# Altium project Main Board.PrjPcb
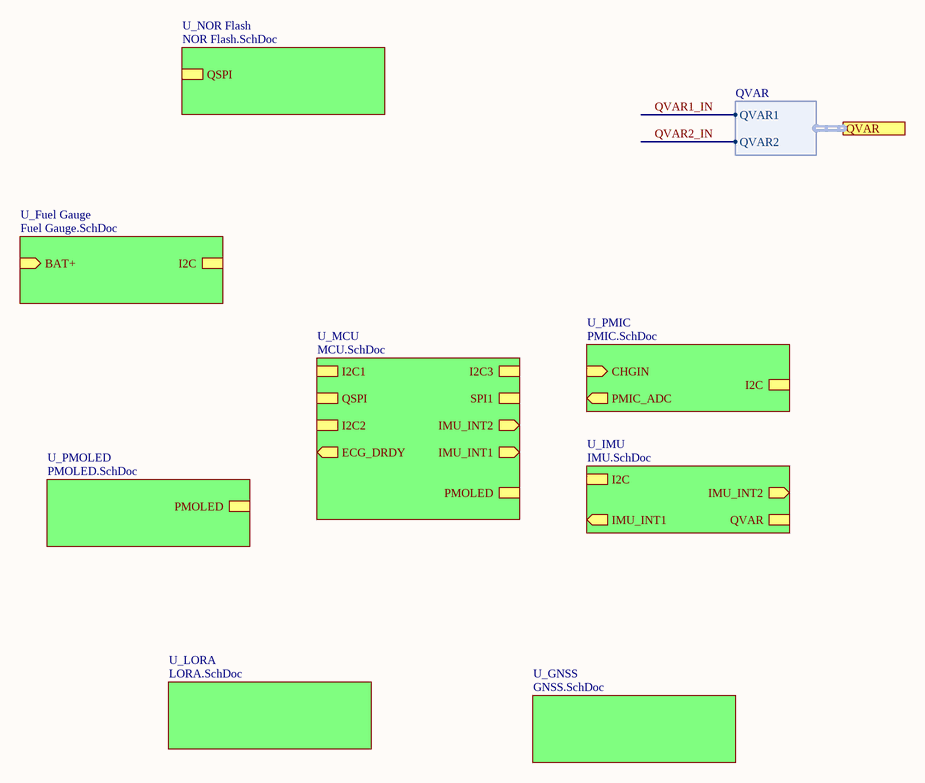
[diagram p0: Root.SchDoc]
9 sheets, 84 parts. Net scope: hierarchical (ports join the sheet entries above them; power ports are global).
Board file: Main Board.PcbDoc
Sheets:
  Root.SchDoc
    U_PMIC = PMIC.SchDoc
    U_MCU = MCU.SchDoc
    U_IMU = IMU.SchDoc
    U_Fuel Gauge = Fuel Gauge.SchDoc
    U_NOR Flash = NOR Flash.SchDoc
    U_PMOLED = PMOLED.SchDoc
    U_GNSS = GNSS.SchDoc
    U_LORA = LORA.SchDoc

## Sheet Root.SchDoc
size A4; SheetNumber: 1; SheetTotal: 9

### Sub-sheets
U_Fuel Gauge = Fuel Gauge.SchDoc: BAT+ (in), I2C (harness I2C)
U_GNSS = GNSS.SchDoc: no entries
U_IMU = IMU.SchDoc: I2C (harness I2C), IMU_INT1 (out), IMU_INT2 (out), QVAR (harness QVAR)
U_LORA = LORA.SchDoc: no entries
U_MCU = MCU.SchDoc: I2C3 (harness I2C), I2C1 (harness I2C), QSPI (harness QSPI), I2C2 (harness I2C), ECG_DRDY (out), IMU_INT1 (out), IMU_INT2 (out), SPI1 (harness SPI), PMOLED (harness PMOLED)
U_NOR Flash = NOR Flash.SchDoc: QSPI (harness QSPI)
U_PMIC = PMIC.SchDoc: CHGIN (in), I2C (harness I2C), PMIC_ADC (out)
U_PMOLED = PMOLED.SchDoc: PMOLED (harness PMOLED)

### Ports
QVAR (harness QVAR)

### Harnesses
QVAR: QVAR2, QVAR1

## Sheet PMIC.SchDoc
size A4; SheetNumber: 3; SheetTotal: 9
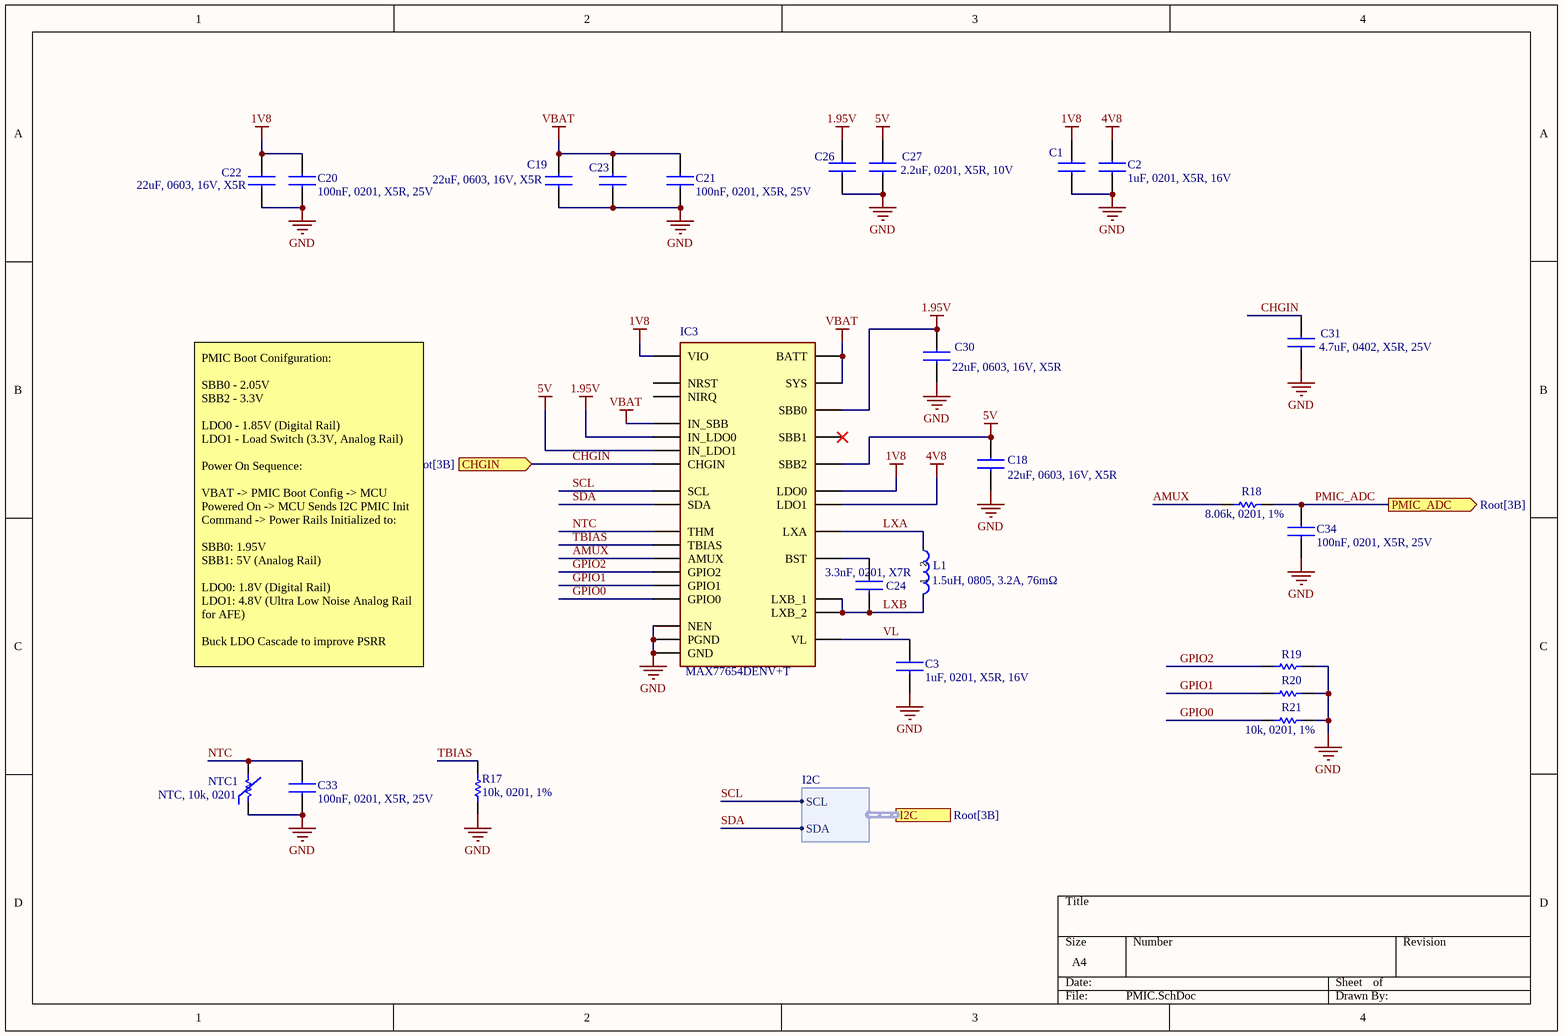
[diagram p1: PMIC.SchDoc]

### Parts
C1  1uF, 0201, X5R, 16V  [CL03A105MQ3CSNH]  (value not drawn)
C2  1uF, 0201, X5R, 16V  [CL03A105MQ3CSNH]
C3  1uF, 0201, X5R, 16V  [CL03A105MQ3CSNH]
C18  22uF, 0603, 16V, X5R  [CAPC1608X80N]
C19  22uF, 0603, 16V, X5R  [CAPC1608X80N]
C20  100nF, 0201, X5R, 25V  [CL03A104KO3NNNC]
C21  100nF, 0201, X5R, 25V  [CL03A104KO3NNNC]
C22  22uF, 0603, 16V, X5R  [CAPC1608X80N]
C23  22uF, 0603, 16V, X5R  [CAPC1608X80N]  (value not drawn)
C24  3.3nF, 0201, X7R  [GCM033R71E332KE02D]
C26  2.2uF, 0201, X5R, 10V  [GRM033R61A225ME47D]  (value not drawn)
C27  2.2uF, 0201, X5R, 10V  [GRM033R61A225ME47D]
C30  22uF, 0603, 16V, X5R  [CAPC1608X80N]
C31  4.7uF, 0402, X5R, 25V  [CL05A106MP5NUNC]
C33  100nF, 0201, X5R, 25V  [CL03A104KO3NNNC]
C34  100nF, 0201, X5R, 25V  [CL03A104KO3NNNC]
IC3  MAX77654DENV+T  [BGA30C40P6X5_279X234X50]
L1  1.5uH, 0805, 3.2A, 76mΩ  [MTQH201210S1R5MBT]
NTC1  NTC, 10k, 0201  [NCP03XH103F05RL]
R17  10k, 0201, 1%  [RC0201FR-0710KL]
R18  8.06k, 0201, 1%  [RC0201FR-078K06L]
R19  10k, 0201, 1%  [RC0201FR-0710KL]  (value not drawn)
R20  10k, 0201, 1%  [RC0201FR-0710KL]  (value not drawn)
R21  10k, 0201, 1%  [RC0201FR-0710KL]

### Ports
CHGIN (in, see Root[3B]), I2C (harness I2C, see Root[3B]), PMIC_ADC (out, see Root[3B])

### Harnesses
I2C: SDA, SCL

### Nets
1.95V: C26.2 C30.2 IC3.B6(IN_LDO0) IC3.C6(SBB0)
1V8: C1.2 C20.2 C22.2 IC3.A4(VIO) IC3.B5(LDO0)
4V8: C2.2 IC3.A5(LDO1)
5V: C18.2 C27.2 IC3.A6(IN_LDO1) IC3.D4(SBB2)
GND: C1.1 C2.1 C3.1 C18.1 C19.1 C20.1 C21.1 C22.1 C23.1 C26.1 C27.1 C30.1 C31.1 C33.1 C34.1 IC3.B3(NEN) IC3.C3(GND) IC3.E6(PGND) NTC1.1 R17.1 R19.1 R20.1 R21.1  [project net SDO]
VBAT: C19.2 C21.2 C23.2 IC3.E2(SYS) IC3.E3(BATT) IC3.E4(IN_SBB)  [project net I_SENSE_N]
AMUX: IC3.C1(AMUX) R18.1
CHGIN: C31.2 IC3.E1(CHGIN) ; port CHGIN
GPIO0: IC3.B1(GPIO0) R21.2
GPIO1: IC3.A1(GPIO1) R20.2
GPIO2: IC3.C2(GPIO2) R19.2
LXA: IC3.E5(LXA) L1.2
LXB: C24.1 IC3.C5(LXB_1) IC3.D5(LXB_2) L1.1
NTC: C33.2 IC3.D2(THM) NTC1.2
PMIC_ADC: C34.2 R18.2 ; port PMIC_ADC
SCL: IC3.B4(SCL) ; port I2C.SCL
SDA: IC3.A3(SDA) ; port I2C.SDA
TBIAS: IC3.D3(TBIAS) R17.2
VL: C3.2 IC3.D1(VL)
NetC24_2: C24.2 IC3.D6(BST)

Not connected (* = marked no-connect by the designer): IC3 A2(NRST) B2(NIRQ) C4(SBB1)*

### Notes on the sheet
- PMIC Boot Conifguration:
  SBB0 - 2.05V
  SBB2 - 3.3V
  LDO0 - 1.85V (Digital Rail)
  LDO1 - Load Switch (3.3V, Analog Rail)
  Power On Sequence:
  VBAT -> PMIC Boot Config -> MCU Powered On -> MCU Sends I2C PMIC Init Command -> Power Rails Initialized to:
  SBB0: 1.95V
  SBB1: 5V (Analog Rail)
  LDO0: 1.8V (Digital Rail)
  LDO1: 4.8V (Ultra Low Noise Analog Rail                                                              for AFE)
  Buck LDO Cascade to improve PSRR

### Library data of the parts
C1-C3 = GRM033R61C105ME15D: Manufacturer_Name: muRata
C18 C19 C22 C23 C30 = CL10A226MO7JZNC: Multilayer Ceramic Capacitors MLCC - SMD/SMT 22uF+/-20% 16V X5R 1608; Manufacturer_Name: SAMSUNG
C20 C21 C33 C34 = CL03A104KO3NNNC: CAP CER 100nF 25V X5R 0201; Manufacturer_Name: SAMSUNG; Manu Part #: CL03A104KA3NNNC
C24 = GCM033R71E332KE02D: Manufacturer_Name: Murata Electronics
C26 C27 = GRM033R61A225ME47D: Manufacturer_Name: Murata Electronics
C31 = GRM155R61E475ME15D: 4.7uF ±20% 25V Ceramic Capacitor X5R 0402
IC3 = MAX77654DENV+T: Power Management Specialised - PMIC Ultra Low Power PMIC w/ 3-Output SIMO + Linear Charger; Manufacturer_Name: Analog Devices
L1 = MTQH201210S1R5MBT: 1.5uH 2.6A 3.2A 76mΩ Molded Inductor ±20% 0805 Power Inductors ROHS; Manufacturer: MetalLions; ki_keywords: C17701177 L0805 MTQH201210S1R5MBT MetalLions
NTC1 = NCP03XH103F05RL: THERMISTOR NTC 10kΩ 3380K 0201; Manufacturer_Name: Murata Electronics
R17 R19-R21 = RC0201FR-0710KL
R18 = RC0201FR-078K06L: Manufacturer_Name: Yageo Group

## Sheet MCU.SchDoc
size C; SheetNumber: 2; SheetTotal: 8
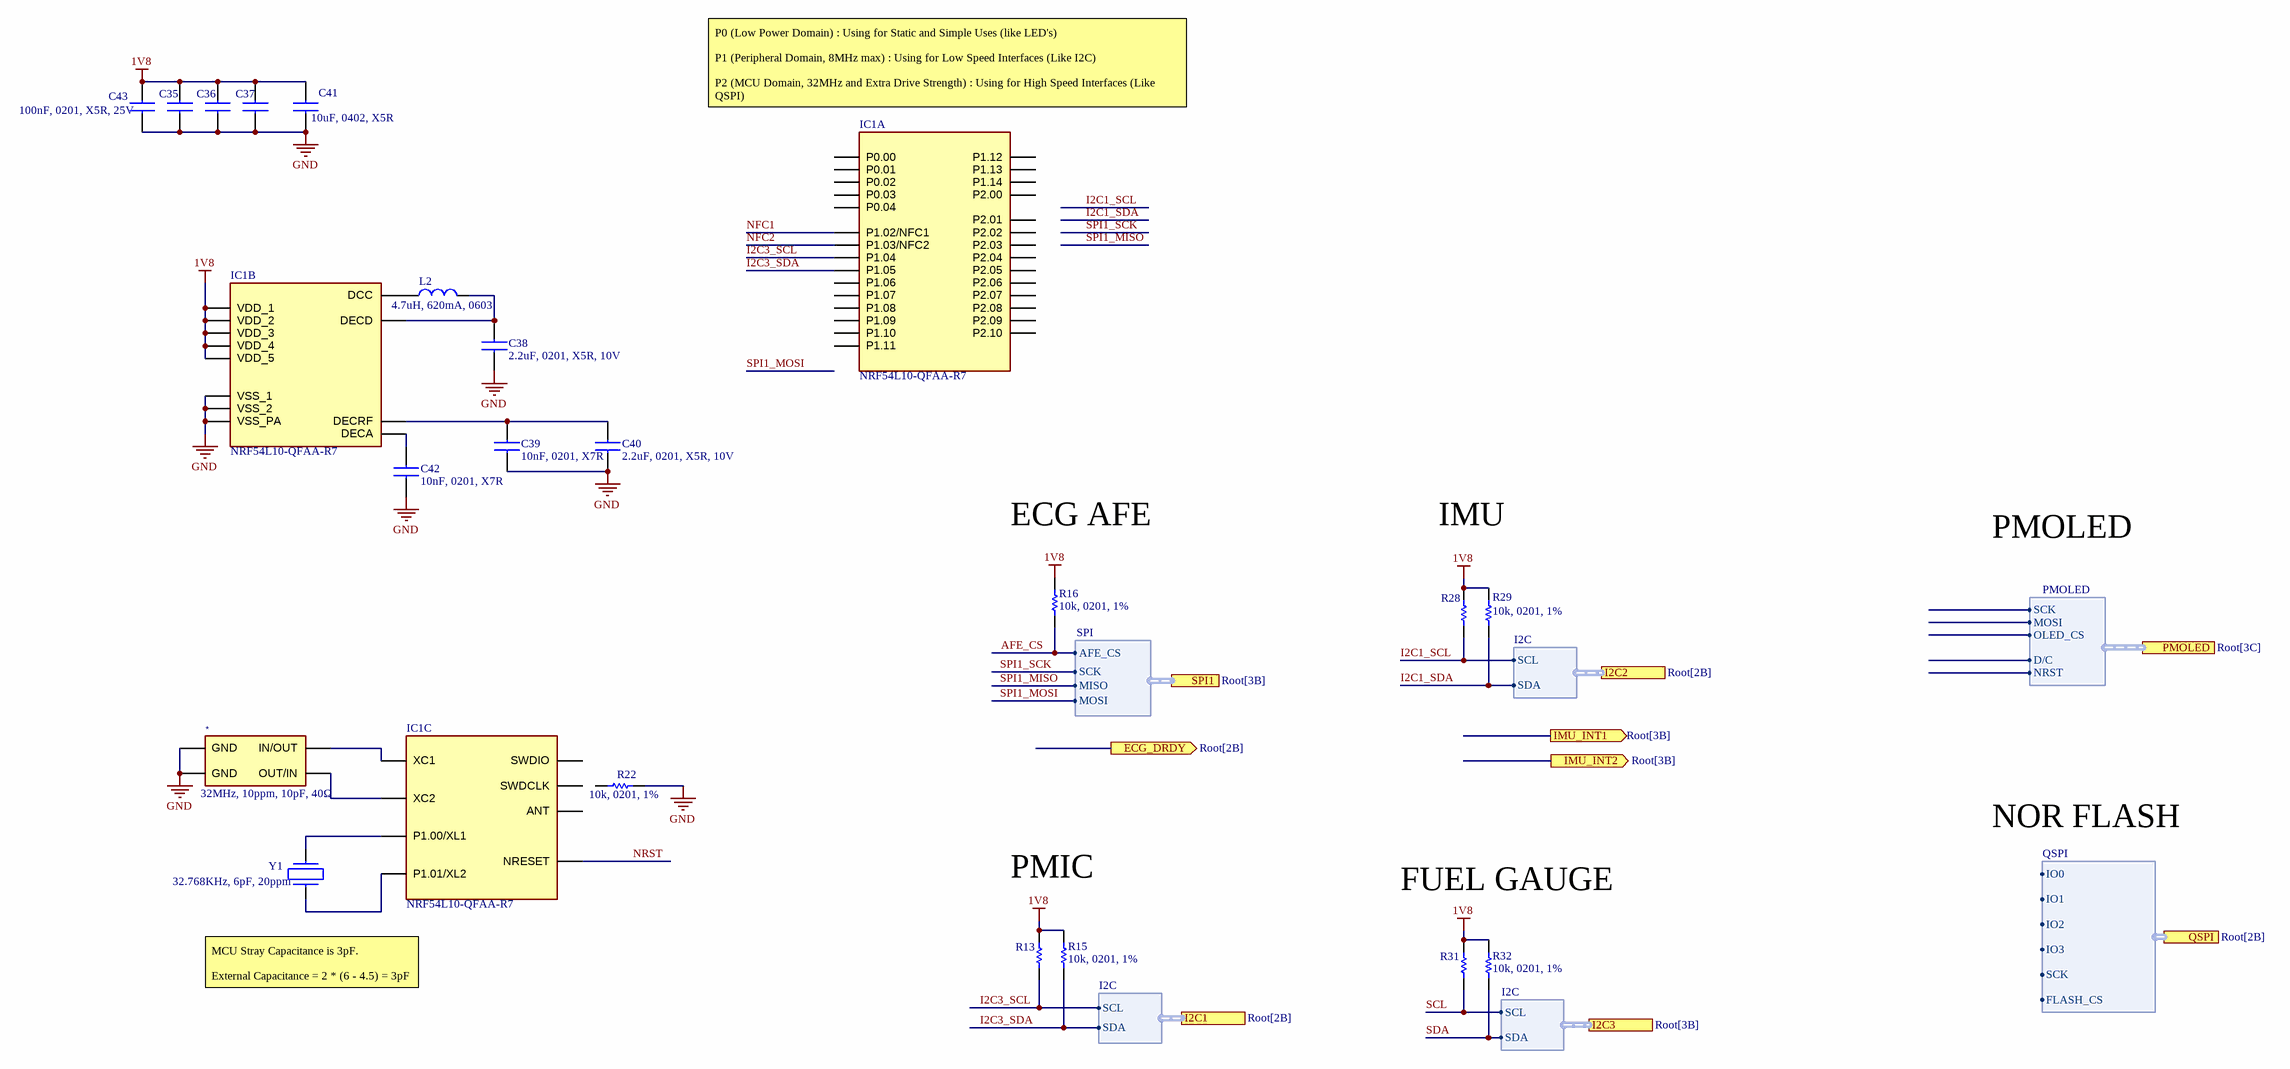
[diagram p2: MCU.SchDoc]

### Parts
(Parts that share a designator on the sheet are numbered #1, #2 ... from top to bottom, then left to right.)
*#1  32MHz, 10ppm, 10pF, 40Ω  [Q24FA20H0021700]
C35  100nF, 0201, X5R, 25V  [CL03A104KO3NNNC]  (value not drawn)
C36  100nF, 0201, X5R, 25V  [CL03A104KO3NNNC]  (value not drawn)
C37  100nF, 0201, X5R, 25V  [CL03A104KO3NNNC]  (value not drawn)
C38  2.2uF, 0201, X5R, 10V  [GRM033R61A225ME47D]
C39  10nF, 0201, X7R  [CL03A105MQ3CSNH]
C40  2.2uF, 0201, X5R, 10V  [GRM033R61A225ME47D]
C41  10uF, 0402, X5R  [CL05A106MP5NUNC]
C42  10nF, 0201, X7R  [CL03A105MQ3CSNH]
C43  100nF, 0201, X5R, 25V  [CL03A104KO3NNNC]
IC1  NRF54L10-QFAA-R7  [NRF54L10-QFAA-R7]  (parts A,B,C of 3)
L2  4.7uH, 620mA, 0603  [LQM18PH1R0MFRB]
R13  10k, 0201, 1%  [RC0201FR-0710KL]  (value not drawn)
R15  10k, 0201, 1%  [RC0201FR-0710KL]
R16  10k, 0201, 1%  [RC0201FR-0710KL]
R22  10k, 0201, 1%  [RC0201FR-0710KL]
R28  10k, 0201, 1%  [RC0201FR-0710KL]  (value not drawn)
R29  10k, 0201, 1%  [RC0201FR-0710KL]
R31  10k, 0201, 1%  [RC0201FR-0710KL]  (value not drawn)
R32  10k, 0201, 1%  [RC0201FR-0710KL]
Y1  32.768KHz, 6pF, 20ppm  [Q13FC1350004900]

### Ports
ECG_DRDY (out, see Root[2B]), I2C1 (harness I2C, see Root[2B]), I2C2 (harness I2C, see Root[2B]), I2C3 (harness I2C, see Root[3B]), IMU_INT1 (out, see Root[3B]), IMU_INT2 (out, see Root[3B]), PMOLED (harness PMOLED, see Root[3C]), QSPI (harness QSPI, see Root[2B]), SPI1 (harness SPI, see Root[3B])

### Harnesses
I2C: SCL, SDA
SPI: MOSI, MISO, SCK, AFE_CS
I2C: SDA, SCL
QSPI: FLASH_CS, SCK, IO3, IO2, IO1, IO0
PMOLED: SCK, MOSI, OLED_CS, NRST, D/C

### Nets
1V8: C35.2 C36.2 C37.2 C41.1 C43.2 IC1.10(VDD_1) IC1.22(VDD_2) IC1.36(VDD_3) IC1.47(VDD_4) IC1.48(VDD_5) R13.2 R15.2 R16.2 R28.2 R29.2 R31.2 R32.2
GND: *#1.2(GND) *#1.4(GND) C35.1 C36.1 C37.1 C38.1 C39.1 C40.1 C41.2 C42.1 C43.1 IC1.32(VSS_PA) IC1.44(VSS_1) IC1.49(VSS_2) R22.2  [project net SDO]
AFE_CS: R16.1 ; port SPI1.AFE_CS
I2C1_SCL: R28.1 ; port I2C2.SCL
I2C1_SDA: R29.1 ; port I2C2.SDA
I2C3_SCL: IC1.5(P1.04) R13.1 ; port I2C1.SCL
I2C3_SDA: IC1.6(P1.05) R15.1 ; port I2C1.SDA
NFC1: IC1.3(P1.02/NFC1)
NFC2: IC1.4(P1.03/NFC2)
NRST: IC1.30(NRESET)
SCL: R31.1 ; port I2C3.SCL
SDA: R32.1 ; port I2C3.SDA
Net*#1_1: *#1.1(IN/OUT) IC1.34(XC1)
Net*#1_3: *#1.3(OUT/IN) IC1.35(XC2)
NetC38_2: C38.2 IC1.45(DECD) L2.2
NetC39_2: C39.2 C40.2 IC1.33(DECRF)
NetC42_2: C42.2 IC1.43(DECA)
NetIC1_1: IC1.1(P1.00/XL1) Y1.2
NetIC1_2: IC1.2(P1.01/XL2) Y1.1
NetIC1_46: IC1.46(DCC) L2.1

Not connected (* = marked no-connect by the designer): IC1 7(P1.06) 8(P1.07) 9(P1.08) 11(P2.00) 12(P2.01) 13(P2.02) 14(P2.03) 15(P2.04) 16(P2.05) 17(P2.06) 18(P2.07) 19(P2.08) 20(P2.09) 21(P2.10) 23(P0.00) 24(P0.01) 25(SWDIO) 26(SWDCLK) 27(P0.02) 28(P0.03) 29(P0.04) 31(ANT) 37(P1.09) 38(P1.10) 39(P1.11) 40(P1.12) 41(P1.13) 42(P1.14); R22 1

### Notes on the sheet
- P0 (Low Power Domain) : Using for Static and Simple Uses (like LED's)
  P1 (Peripheral Domain, 8MHz max) : Using for Low Speed Interfaces (Like I2C)
  P2 (MCU Domain, 32MHz and Extra Drive Strength) : Using for High Speed Interfaces (Like QSPI)
- ECG AFE
- IMU
- PMOLED
- PMIC
- NOR FLASH
- FUEL GAUGE
- MCU Stray Capacitance is 3pF.
  External Capacitance = 2 * (6 - 4.5) = 3pF

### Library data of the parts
*#1 = Q24FA20H0021700: -40℃~+85℃ 10pF 32MHz 40Ω Crystal Oscillator ±10ppm ±20ppm SMD2520-4P Crystals ROHS; Manufacturer: Seiko Epson
C35-C37 C43 = CL03A104KO3NNNC: as C20 on sheet PMIC
C38 C40 = GRM033R61A225ME47D: Manufacturer_Name: Murata Electronics
C39 C42 = CC0201KRX7R8BB103: Manufacturer_Name: YAGEO
C41 = CL05A106MP5NUNC: Manufacturer_Name: SAMSUNG
IC1 = NRF54L10-QFAA-R7: IC RF TxRx + MCU 802.15.4, Bluetooth Bluetooth v6.0, Matter, Thread 48-VFQFN Exposed Pad; Manufacturer_Name: Nordic Semiconductor
L2 = LQM18PN4R7MFRL: FIXED IND 4.7uH 620mA 440mΩ 0603; Manufacturer_Name: Murata Electronics
R13 R15 R16 R22 R28 R29 R31 R32 = RC0201FR-0710KL
Y1 = Q13FC1350004900: -40℃~+85℃ 32.768kHz 6pF 70kΩ Crystal Oscillator ±20ppm SMD3215-2P Crystals ROHS; Manufacturer: Seiko Epson

## Sheet IMU.SchDoc
size A; SheetNumber: 5; SheetTotal: 8
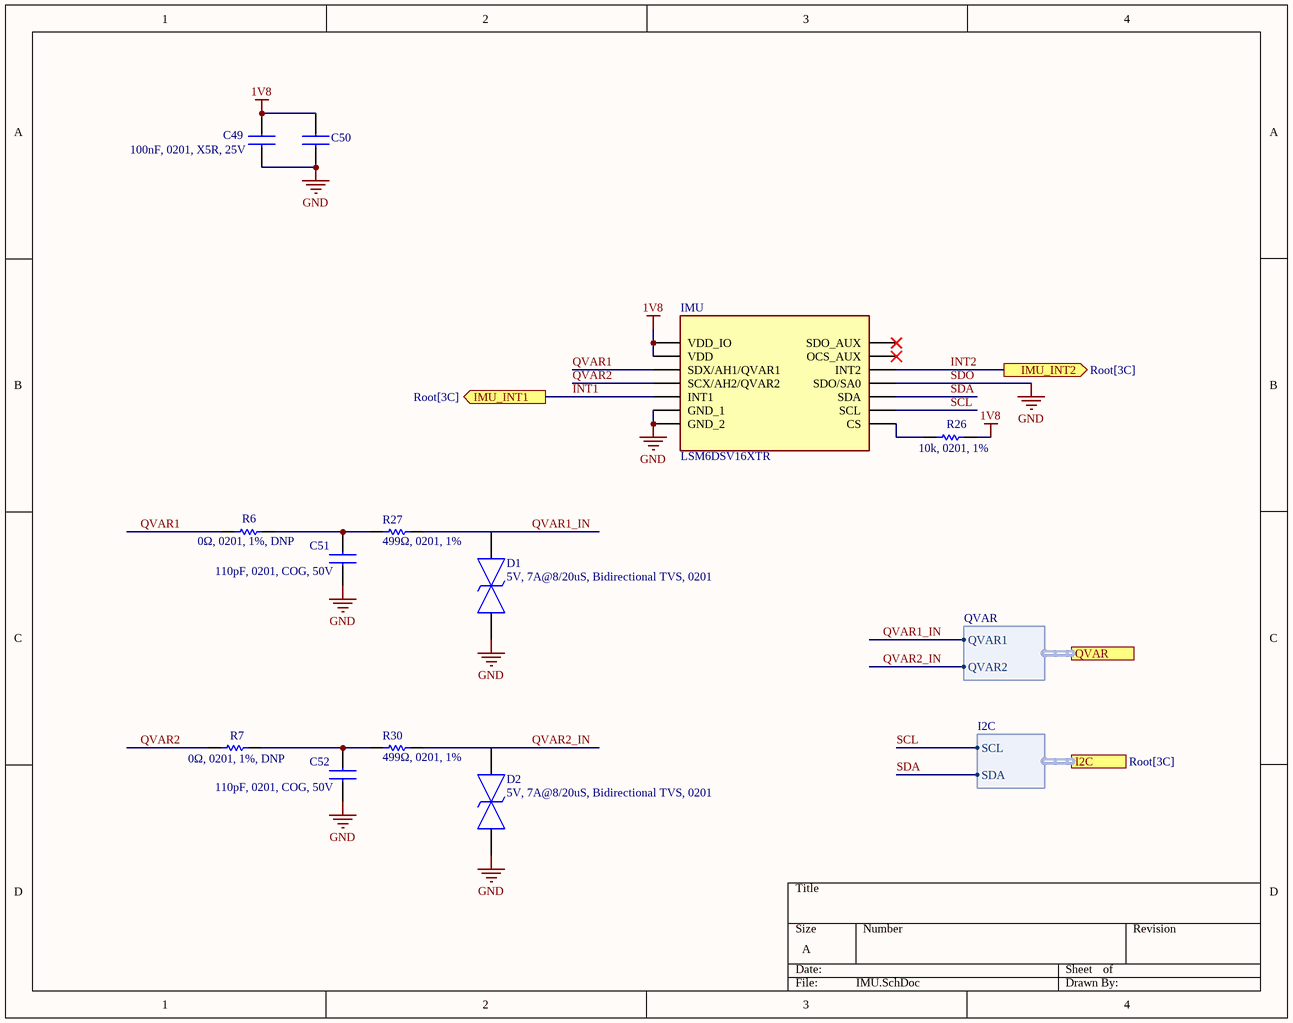
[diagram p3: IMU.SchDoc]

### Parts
C49  100nF, 0201, X5R, 25V  [CL03A104KO3NNNC]
C50  CL03A104KO3NNNC  [CL03A104KO3NNNC]  (value not drawn)
C51  110pF, 0201, COG, 50V  [GRM0335C1H111GA01D]
C52  110pF, 0201, COG, 50V  [GRM0335C1H111GA01D]
D1  5V, 7A@8/20uS, Bidirectional TVS, 0201  [B74121U0033M060]
D2  5V, 7A@8/20uS, Bidirectional TVS, 0201  [B74121U0033M060]
IMU  LSM6DSV16XTR  [LSM6DSV16BXTR]
R6  0Ω, 0201, 1%, DNP  [RC0201FR-070RL]
R7  0Ω, 0201, 1%, DNP  [RC0201FR-070RL]
R26  10k, 0201, 1%  [RC0201FR-0710KL]
R27  499Ω, 0201, 1%  [RC0201FR-07499RL]
R30  499Ω, 0201, 1%  [RC0201FR-07499RL]

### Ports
I2C (harness I2C, see Root[3C]), IMU_INT1 (out, see Root[3C]), IMU_INT2 (out, see Root[3C]), QVAR (harness QVAR)

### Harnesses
I2C: SDA, SCL
QVAR: QVAR2, QVAR1

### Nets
1V8: C49.2 C50.2 IMU.5(VDD_IO) IMU.8(VDD) R26.1
SDO: C49.1 C50.1 C51.1 C52.1 IMU.1(SDO/SA0) IMU.6(GND_1) IMU.7(GND_2)  [also labelled GND]
INT1: IMU.4(INT1) ; port IMU_INT1
INT2: IMU.9(INT2) ; port IMU_INT2
QVAR1: IMU.2(SDX/AH1/QVAR1) R6.1
QVAR1_IN: R27.2 ; port QVAR.QVAR1
QVAR2: IMU.3(SCX/AH2/QVAR2) R7.1
QVAR2_IN: R30.2 ; port QVAR.QVAR2
SCL: IMU.13(SCL) ; port I2C.SCL
SDA: IMU.14(SDA) ; port I2C.SDA
NetC51_2: C51.2 R6.2 R27.1
NetC52_2: C52.2 R7.2 R30.1
NetIMU_12: IMU.12(CS) R26.2

Not connected (* = marked no-connect by the designer): D1 A1(I/O) B1(GND); D2 A1(I/O) B1(GND); IMU 10(OCS_AUX)* 11(SDO_AUX)*

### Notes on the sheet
- Labels drawn without touching a wire or pin: GND

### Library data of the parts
C49 C50 = CL03A104KO3NNNC: as C20 on sheet PMIC
C51 C52 = GRM0335C1H111GA01D: 110pF C0G ±2% 50V 0201 Ceramic Capacitors RoHS
D1 D2 = B74121U0033M060: -40℃~+125℃ 0.65pF 1 1nA 3.3V 5.2V 5V 7A@8/20us Bidirectional IEC 61000-4-2、IEC 61000-4-5 TVS 0201 ESD and Surge Protection (TVS/ESD) ROHS; Manufacturer_Name: TDK
IMU = LSM6DSV16XTR: 6-axis inertial measurement unit (IMU) and Al sensor with embedded sensor fusion, Qvar for high-end applications; Manufacturer_Name: STMicroelectronics
R6 R7 = RC0201FR-070RL: RES 0Ω ±1% 50mW 0201; Manufacturer_Name: YAGEO
R26 = RC0201FR-0710KL
R27 R30 = RC0201FR-07499RL: 50mW 499Ω 25V Thick Film Resistor ±1% ±200ppm/℃ 0201 Chip Resistor - Surface Mount RoHS; Manufacturer_Name: Yageo Group

## Sheet Fuel Gauge.SchDoc
size A4; SheetNumber: 6; SheetTotal: 7
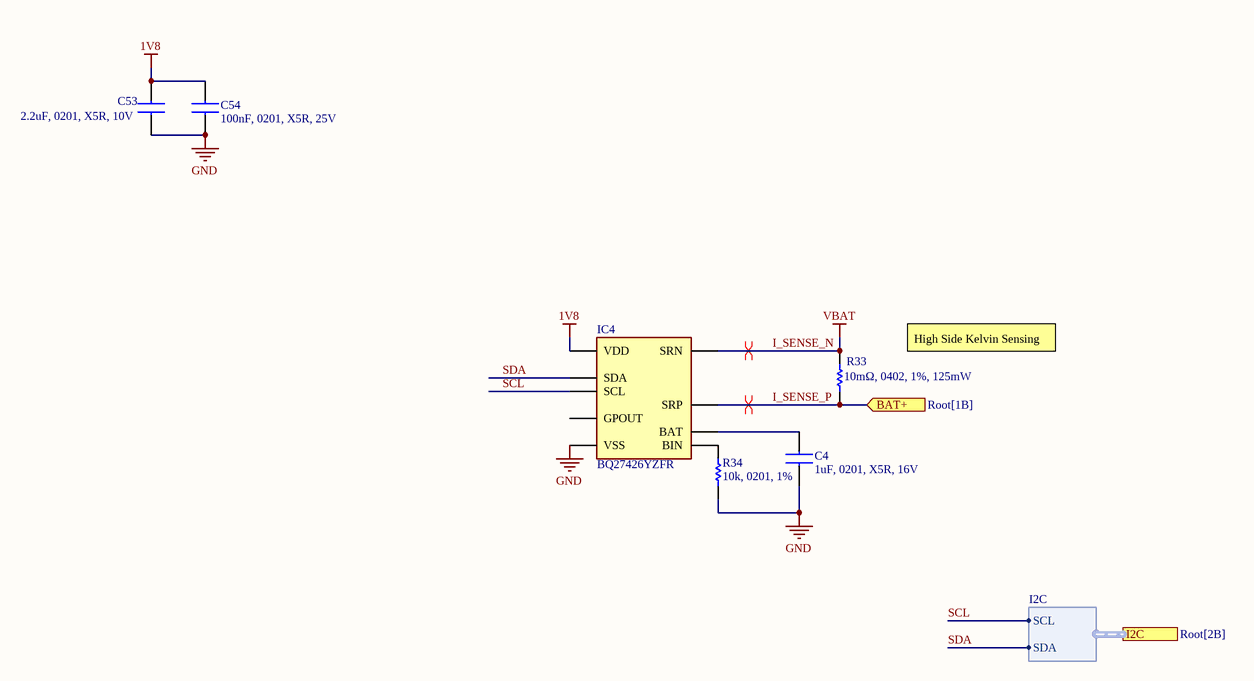
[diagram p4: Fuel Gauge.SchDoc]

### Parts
C4  1uF, 0201, X5R, 16V  [CL03A105MQ3CSNH]
C53  2.2uF, 0201, X5R, 10V  [GRM033R61A225ME47D]
C54  100nF, 0201, X5R, 25V  [CL03A104KO3NNNC]
IC4  BQ27426YZFR  [BQ27426YZFR]
R33  10mΩ, 0402, 1%, 125mW  [CSRF0402FT10L0]
R34  10k, 0201, 1%  [RC0201FR-0710KL]

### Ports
BAT+ (in, see Root[1B]), I2C (harness I2C, see Root[2B])

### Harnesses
I2C: SDA, SCL

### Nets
1V8: C53.2 C54.2 IC4.B3(VDD)
GND: C4.1 C53.1 C54.1 IC4.B2(VSS) R34.2  [project net SDO]
I_SENSE_N: IC4.C2(SRN) R33.2  [also labelled VBAT]
I_SENSE_P: IC4.C1(SRP) R33.1 ; port BAT+
SCL: IC4.A3(SCL) ; port I2C.SCL
SDA: IC4.A2(SDA) ; port I2C.SDA
NetC4_2: C4.2 IC4.C3(BAT)
NetIC4_B1: IC4.B1(BIN) R34.1

Not connected (* = marked no-connect by the designer): IC4 A1(GPOUT)

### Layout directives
differential pair: I_SENSE_N, I_SENSE_P

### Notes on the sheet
- High Side Kelvin Sensing

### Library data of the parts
C4 = GRM033R61C105ME15D: Manufacturer_Name: muRata
C53 = GRM033R61A225ME47D: Manufacturer_Name: Murata Electronics
C54 = CL03A104KO3NNNC: as C20 on sheet PMIC
IC4 = BQ27426YZFR: Single cell System-Side Battery Fuel (Gas) Gauge w/Pre-programmed Chemistry Profile; Manufacturer_Name: Texas Instruments
R33 = CSRF0402FT10L0: RES 10mΩ ±1% 125mW 0402; Manufacturer_Name: Stackpole Electronics
R34 = RC0201FR-0710KL

## Sheet NOR Flash.SchDoc
size A4; SheetNumber: 7; SheetTotal: 9
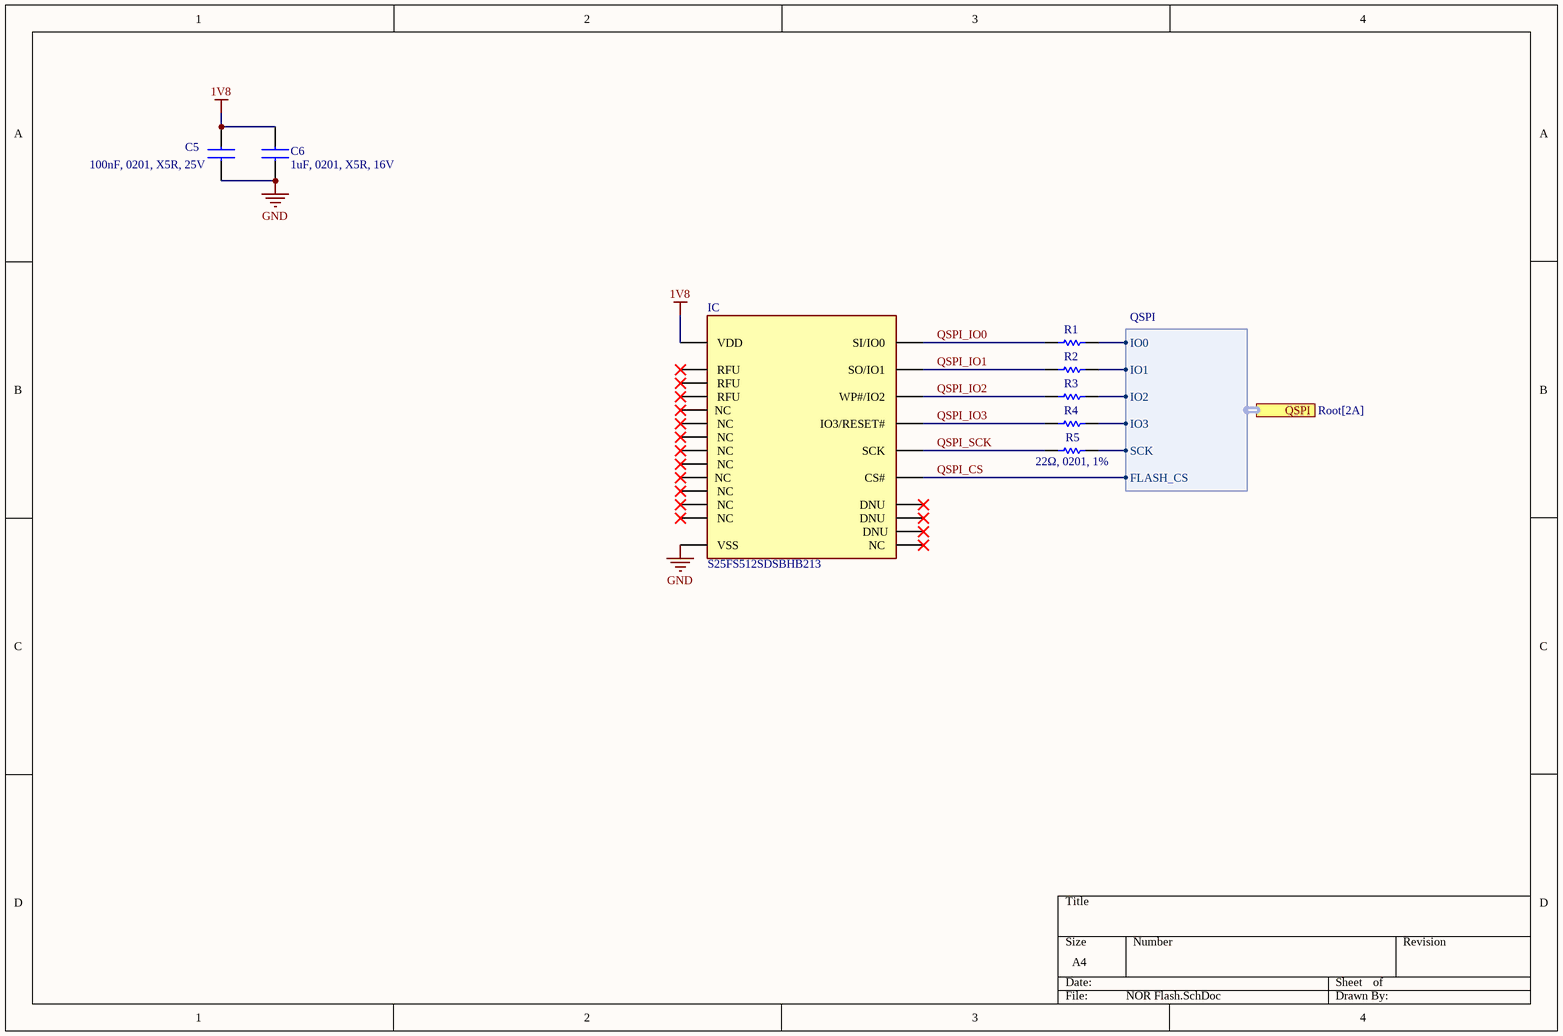
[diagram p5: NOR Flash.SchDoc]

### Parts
C5  100nF, 0201, X5R, 25V  [CL03A104KO3NNNC]
C6  1uF, 0201, X5R, 16V  [CL03A105MQ3CSNH]
IC  S25FS512SDSBHB213  [S25FS512SDSBHB213]
R1  22Ω, 0201, 1%  [AF0201FR-071M5L]  (value not drawn)
R2  22Ω, 0201, 1%  [AF0201FR-071M5L]  (value not drawn)
R3  22Ω, 0201, 1%  [AF0201FR-071M5L]  (value not drawn)
R4  22Ω, 0201, 1%  [AF0201FR-071M5L]  (value not drawn)
R5  22Ω, 0201, 1%  [AF0201FR-071M5L]

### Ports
QSPI (harness QSPI, see Root[2A])

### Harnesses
QSPI: FLASH_CS, SCK, IO3, IO2, IO1, IO0

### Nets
1V8: C5.2 C6.2 IC.B4(VDD)
GND: C5.1 C6.1 IC.B3(VSS)  [project net SDO]
QSPI_CS: IC.C2(CS#) ; port QSPI.FLASH_CS
QSPI_IO0: IC.D3(SI/IO0) R1.1
QSPI_IO1: IC.D2(SO/IO1) R2.1
QSPI_IO2: IC.C4(WP#/IO2) R3.1
QSPI_IO3: IC.D4(IO3/RESET#) R4.1
QSPI_SCK: IC.B2(SCK) R5.1
NetR1_2: R1.2 ; port QSPI.IO0
NetR2_2: R2.2 ; port QSPI.IO1
NetR3_2: R3.2 ; port QSPI.IO2
NetR4_2: R4.2 ; port QSPI.IO3
NetR5_2: R5.2 ; port QSPI.SCK

Not connected (* = marked no-connect by the designer): IC A2(NC)* A3(NC)* A4(RFU)* A5(NC)* B1(DNU)* B5(NC)* C1(DNU)* C3(RFU)* C5(NC)* D1(DNU)* D5(NC)* E1(NC)* E2(NC)* E3(NC)* E4(RFU)* E5(NC)*

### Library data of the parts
C5 = CL03A104KO3NNNC: as C20 on sheet PMIC
C6 = GRM033R61C105ME15D: Manufacturer_Name: muRata
IC = S25FS512SDSBHB213: -40℃~+105℃ 1.7V~2V 512Mbit SPI TBGA-24 NOR FLASH ROHS; Manufacturer: Infineon/Cypress Semicon
R1-R5 = RC0201FR-0722RL: RES 22Ω ±1% 50mW 0201

## Sheet PMOLED.SchDoc
size A4; SheetNumber: 4; SheetTotal: 8
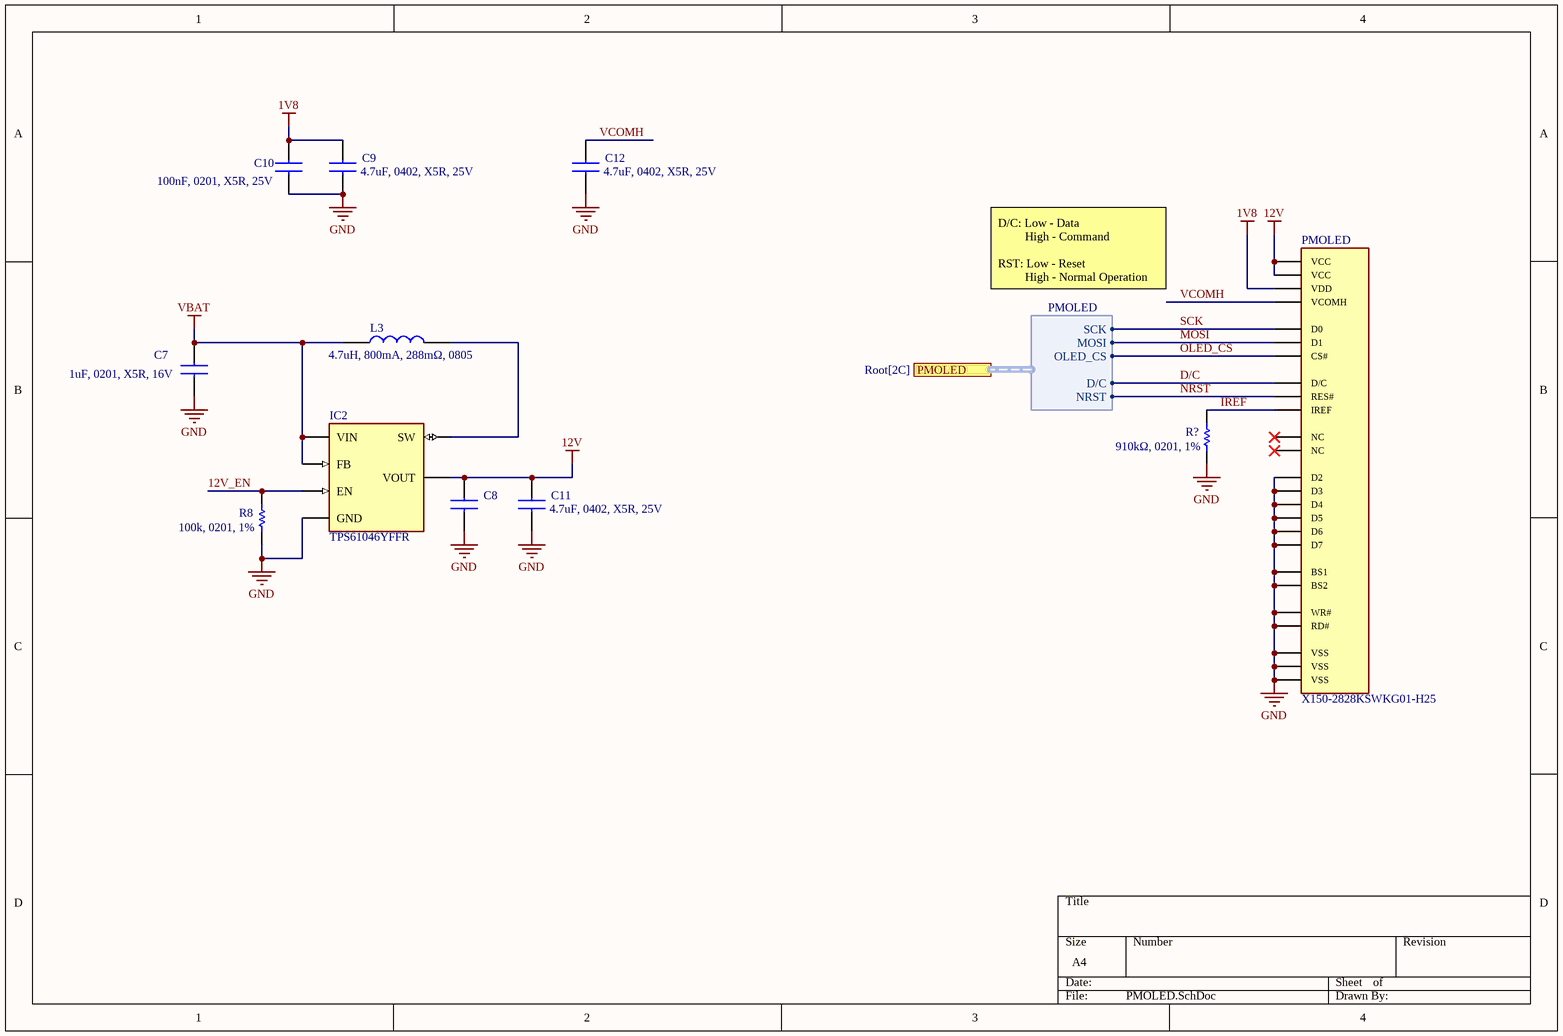
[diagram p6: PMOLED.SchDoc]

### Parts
C7  1uF, 0201, X5R, 16V  [CL03A105MQ3CSNH]
C8  4.7uF, 0402, X5R, 25V  [CL05A106MP5NUNC]  (value not drawn)
C9  4.7uF, 0402, X5R, 25V  [CL05A106MP5NUNC]
C10  100nF, 0201, X5R, 25V  [CL03A104KO3NNNC]
C11  4.7uF, 0402, X5R, 25V  [CL05A106MP5NUNC]
C12  4.7uF, 0402, X5R, 25V  [CL05A106MP5NUNC]
IC2  TPS61046YFFR  [BGA6C40P2X3_88X123X62]
L3  4.7uH, 800mA, 288mΩ, 0805  [LQM21PHR47NG0D]
PMOLED  X150-2828KSWKG01-H25  [X150-2828KSWKG01-H25]
R8  100k, 0201, 1%  [RC0201FR-0710KL]
R?  910kΩ, 0201, 1%  [0201WMF9103TEE]

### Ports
PMOLED (harness PMOLED, see Root[2C])

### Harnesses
PMOLED: SCK, MOSI, OLED_CS, NRST, D/C

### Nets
1V8: C9.2 C10.2 PMOLED.5(VDD)
12V: C8.2 C11.2 IC2.C2(VOUT) PMOLED.2(VCC) PMOLED.24(VCC)
GND: C7.1 C8.1 C9.1 C10.1 C11.1 C12.1 IC2.A2(GND) PMOLED.1(VSS) PMOLED.7(BS1) PMOLED.8(BS2) PMOLED.9(VSS) PMOLED.14(WR#) PMOLED.15(RD#) PMOLED.18(D2) PMOLED.19(D3) PMOLED.20(D4) PMOLED.21(D5) PMOLED.22(D6) PMOLED.23(D7) PMOLED.25(VSS) R8.1 R?.1  [project net SDO]
VBAT: C7.2 IC2.A1(VIN) IC2.B1(FB) L3.1  [project net I_SENSE_N]
12V_EN: IC2.C1(EN) R8.2
D/C: PMOLED.13(D/C) ; port PMOLED.D/C
IREF: PMOLED.10(IREF) R?.2
MOSI: PMOLED.17(D1) ; port PMOLED.MOSI
NRST: PMOLED.12(RES#) ; port PMOLED.NRST
OLED_CS: PMOLED.11(CS#) ; port PMOLED.OLED_CS
SCK: PMOLED.16(D0) ; port PMOLED.SCK
VCOMH: C12.2 PMOLED.3(VCOMH)
NetIC2_B2: IC2.B2(SW) L3.2

Not connected (* = marked no-connect by the designer): PMOLED 4(NC)* 6(NC)*

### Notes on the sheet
- D/C: Low - Data
  High - Command
  RST: Low - Reset
  High - Normal Operation

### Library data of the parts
C7 = GRM033R61C105ME15D: Manufacturer_Name: muRata
C8 C9 C11 C12 = GRM155R61E475ME15D: as C31 on sheet PMIC
C10 = CL03A104KO3NNNC: as C20 on sheet PMIC
IC2 = TPS61046YFFR: 28-V Output Voltage Boost Converter in WCSP Package; Manufacturer_Name: Texas Instruments
L3 = LQM21PN4R7MGRD: FIXED IND 4.7uH 800mA 288mΩ 0805; Manufacturer_Name: Murata Electronics
PMOLED = X150-2828KSWKG01-H25: -40℃~+70℃ 1.54 100cd/m2 128x128 26.855x26.855mm Passive (PMOLED) SH1107 chip White - OLED Display ROHS; Manufacturer: Newvisio
R8 = RC0201FR-07100KL: Manufacturer_Name: Yageo Group
R? = 0201WMF9103TEE: RES 910kΩ ±1% 50mW 0201; Manufacturer_Name: UNI-ROYAL

## Sheet GNSS.SchDoc
size A4; SheetNumber: 8; SheetTotal: 9
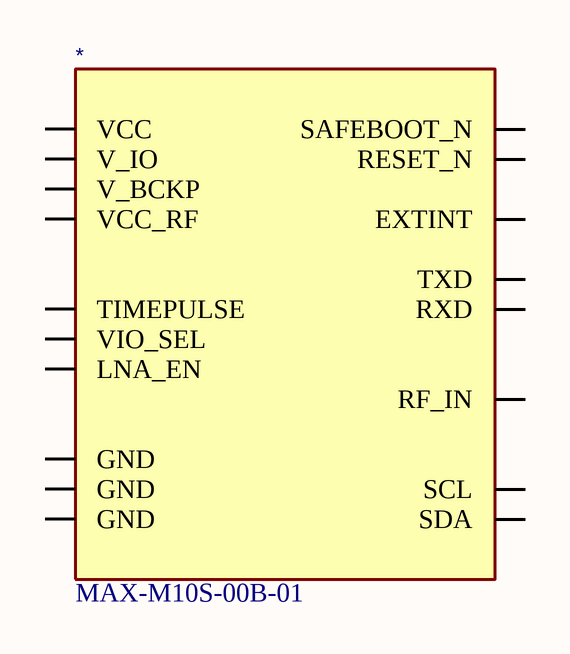
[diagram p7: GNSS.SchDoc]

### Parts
(Parts that share a designator on the sheet are numbered #1, #2 ... from top to bottom, then left to right.)
*#2  MAX-M10S-00B-01  [MAX-M10S-00B-01]

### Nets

Not connected (* = marked no-connect by the designer): *#2 1(GND) 2(TXD) 3(RXD) 4(TIMEPULSE) 5(EXTINT) 6(V_BCKP) 7(V_IO) 8(VCC) 9(RESET_N) 10(GND) 11(RF_IN) 12(GND) 13(LNA_EN) 14(VCC_RF) 15(VIO_SEL) 16(SDA) 17(SCL) 18(SAFEBOOT_N)

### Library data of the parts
*#2 = MAX-M10S-00B-01: MAX-M10 RF Receiver BeiDou, Galileo, GLONASS, GPS, GNSS 1.561GHz, 1.575GHz, 1.602GHz -167dBm 921.6kbps Module; Manufacturer: U-BLOX

## Sheet LORA.SchDoc
size A4; SheetNumber: 9; SheetTotal: 9
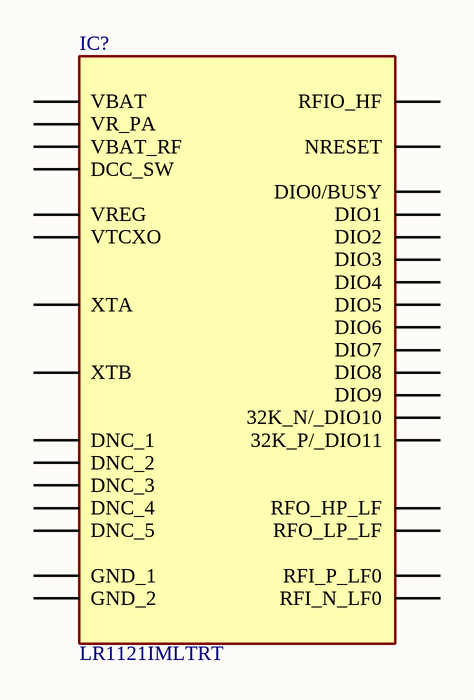
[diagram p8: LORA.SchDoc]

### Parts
IC?  LR1121IMLTRT  [QFN50P500X500X100-33N-D]

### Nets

Not connected (* = marked no-connect by the designer): IC? 1(VR_PA) 2(VBAT_RF) 3(VTCXO) 4(XTA) 5(XTB) 6(NRESET) 7(32K_P/_DIO11) 8(32K_N/_DIO10) 9(DIO9) 10(DIO8) 11(DIO7) 12(VREG) 13(GND_1) 14(DCC_SW) 15(VBAT) 16(DNC_1) 17(DNC_2) 18(DNC_3) 19(DIO6) 20(DIO5) 21(DIO4) 22(DIO3) 23(DIO2) 24(DIO1) 25(DIO0/BUSY) 26(RFIO_HF) 27(DNC_4) 28(DNC_5) 29(RFI_N_LF0) 30(RFI_P_LF0) 31(RFO_LP_LF) 32(RFO_HP_LF) 33(GND_2)

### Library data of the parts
IC? = LR1121IMLTRT: -108dBm -40℃~+85℃ 1.8V~3.7V 101.5Kbps 13dBm 150MHz~960MHz、1.9GHz~2.1GHz、2.4GHz~2.5GHz 26mA 7.8mA LoRa SPI transceiver QFN-32-EP(5x5) RF Transceiver ICs ROHS; Manufacturer_Name: SEMTECH

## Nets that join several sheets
1V8: PMIC (5 pins), MCU (17 pins), IMU (5 pins), Fuel Gauge (C53.2 C54.2 IC4.B3), NOR Flash (C5.2 C6.2 IC.B4), PMOLED (C9.2 C10.2 PMOLED.5)
I_SENSE_N: PMIC (6 pins), Fuel Gauge (IC4.C2 R33.2), PMOLED (C7.2 IC2.A1 IC2.B1 L3.1)
SDO: PMIC (23 pins), MCU (15 pins), IMU (7 pins), Fuel Gauge (5 pins), NOR Flash (C5.1 C6.1 IC.B3), PMOLED (22 pins)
